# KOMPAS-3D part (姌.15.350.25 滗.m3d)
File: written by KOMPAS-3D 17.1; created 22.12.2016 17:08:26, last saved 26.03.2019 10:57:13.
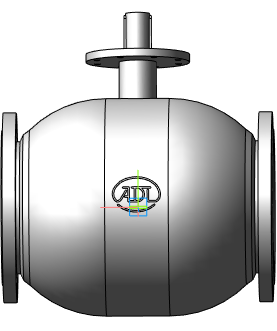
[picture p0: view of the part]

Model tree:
1. Операция без истории:3  (labels: Сталь 20  ГОСТ 1050-88)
